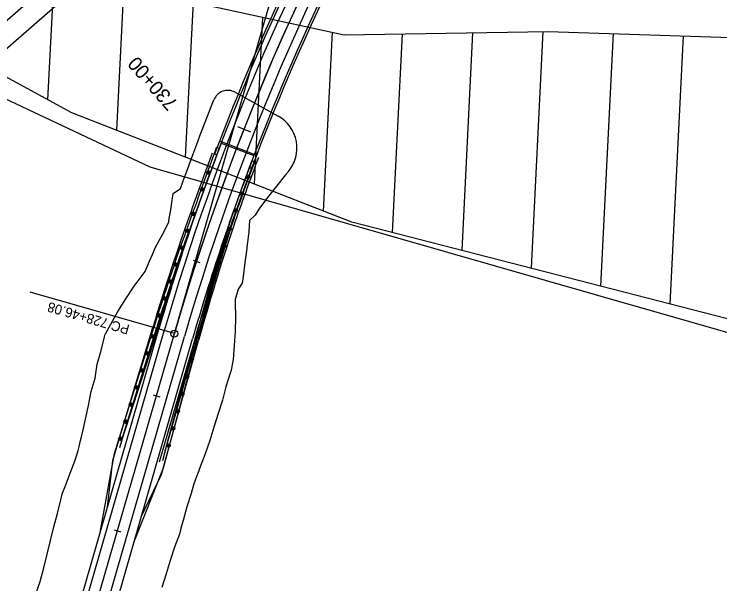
# Model space of a CAD drawing. Extents: x 1300404 to 1323571, y 237813 to 252077.
# Drawn here: x 1311456 to 1311959, y 241084 to 241490 of the extents above; entities that cross this region are included whole.
import ezdxf

# ---------------------------------------------------------------- set-up
doc = ezdxf.new("R2010")
doc.units = 0
for name, color, linetype in [('R_Bridge', 7, 'Continuous'), ('R_Const Limits', 7, 'Continuous'), ('R_Floodway', 7, 'Continuous'), ('R_Flooplain', 7, 'Continuous'), ('R_Future', 7, 'Continuous'), ('R_Guardrail', 7, 'Continuous'), ('R_Horz Alg Annot', 7, 'Continuous'), ('R_Horz Alg Annot Leader', 7, 'Continuous'), ('R_Horz Alg Major Ticks', 7, 'Continuous'), ('R_Horz Alg Minor Ticks', 7, 'Continuous'), ('R_Horz Alg Station Annot', 7, 'Continuous'), ('R_Horz Alg Tangents', 7, 'Continuous'), ('R_Lane Edge', 7, 'Continuous'), ('R_No Plot', 7, 'Continuous'), ('R_Proposed', 7, 'Continuous'), ('R_Shoulder', 7, 'Continuous')]:
    doc.layers.add(name, color=color, linetype=linetype)

msp = doc.modelspace()

# ---------------------------------------------------------------- linework, layer by layer
at = {"layer": 'R_Bridge'}
for p, q in [((1311602.77, 241399.44), (1311629.06, 241389.36)), ((1311603.88, 241397.94), (1311627.23, 241388.99)), ((1311600.69, 241389.53), (1311599.21, 241390.09)), ((1311624.03, 241380.58), (1311625.51, 241380.01))]:
    msp.add_line(p, q, dxfattribs=at)
for radius, start, end in [(1650.1, 149.19442, 159.34505), (1648.52, 149.19413, 159.34535), (1623.52, 149.18931, 159.35016), (1621.94, 149.189, 159.35047)]:
    msp.add_arc((1313143.24, 240808.04), radius, start, end, dxfattribs=at)
at = {"layer": 'R_Const Limits'}
msp.add_line((1311613.83, 241434.11), (1311644.45, 241417.13), dxfattribs=at)
for points in [[(1311471.45, 241076.33), (1311474.97, 241085.72), (1311474.99, 241085.73), (1311477.4, 241095.43), (1311479.82, 241105.14), (1311482.18, 241114.86), (1311484.67, 241124.55), (1311487.13, 241134.25), (1311489.58, 241143.95), (1311490.58, 241147.93), (1311490.62, 241148.06), (1311492.68, 241153.47), (1311496.26, 241162.84), (1311499.85, 241172.21), (1311501.96, 241178.99), (1311502.01, 241179.12), (1311502.67, 241181.81), (1311503.71, 241186.1), (1311504.35, 241188.71), (1311504.38, 241188.84), (1311505.02, 241191.54), (1311507.27, 241201.3), (1311509.24, 241211.14), (1311511.33, 241220.94), (1311513.97, 241230.59), (1311515.53, 241240.55), (1311518.36, 241250.14), (1311520.73, 241259.86), (1311521.3, 241261.88), (1311521.35, 241262), (1311525.14, 241269), (1311530.3, 241278.02), (1311535.88, 241287.07), (1311541.87, 241295.95), (1311548.28, 241304.67), (1311549.68, 241306.48), (1311549.76, 241306.59), (1311552.86, 241313.92), (1311554.87, 241318.63), (1311556.9, 241323.33), (1311561.71, 241332.46), (1311566.48, 241341.6), (1311566.65, 241342.7), (1311568.12, 241351.79), (1311568.47, 241353.93), (1311568.49, 241354.06), (1311569.72, 241362.02), (1311574.88, 241365.59), (1311576.59, 241370.38), (1311580.06, 241379.94), (1311583.58, 241389.47), (1311587.16, 241398.99), (1311588.97, 241403.74), (1311590.8, 241408.48), (1311598.66, 241428.64), (1311598.66, 241428.64)], [(1311651.8, 241377.7), (1311649.74, 241375.23), (1311643.19, 241367.25), (1311636.81, 241359.17), (1311630.68, 241350.96), (1311628.12, 241346.66), (1311624.12, 241342.86), (1311623.65, 241334.94), (1311623.63, 241334.81), (1311623.36, 241332.72), (1311622.25, 241323.84), (1311622.11, 241322.77), (1311620.76, 241312.88), (1311619.48, 241303), (1311618.86, 241298.06), (1311615.95, 241293.85), (1311613.89, 241286.52), (1311613.85, 241286.4), (1311613.91, 241284.23), (1311614, 241273.97), (1311613.78, 241263.85), (1311613.2, 241253.87), (1311612.37, 241243.8), (1311610.96, 241236.12), (1311610.94, 241235.99), (1311610.37, 241233.98), (1311607.26, 241224.46), (1311604.69, 241214.8), (1311601.67, 241205.26), (1311598.67, 241195.72), (1311595.79, 241186.14), (1311592.51, 241176.68), (1311588.96, 241167.3), (1311587.96, 241164.7), (1311587.91, 241164.58), (1311586.96, 241162.05), (1311585.43, 241157.91), (1311584.47, 241155.3), (1311584.43, 241155.18), (1311582.4, 241148.37), (1311579.42, 241138.82), (1311576.7, 241129.2), (1311575.17, 241123.64), (1311575.13, 241123.51), (1311574.18, 241119.52), (1311570.7, 241110.12), (1311567.48, 241100.64), (1311564.58, 241091.07), (1311561.49, 241081.55)]]:
    msp.add_lwpolyline(points, dxfattribs=at)
for centre, radius, start, end in [((1311608.64, 241424.75), 10.71, 60.988, 158.6797), ((1311631.83, 241394.38), 26.02, 320.149, 60.988)]:
    msp.add_arc(centre, radius, start, end, dxfattribs=at)
at = {"layer": 'R_Floodway'}
for p, q in [((1311480.45, 241428.78), (1311486.99, 241559.2)), ((1311529.43, 241407.02), (1311534.97, 241517.61)), ((1311578.53, 241387.86), (1311584.07, 241498.53)), ((1311627.63, 241368.7), (1311633.59, 241487.69)), ((1311676.74, 241349.54), (1311683.11, 241476.85)), ((1311775.45, 241321.47), (1311783.22, 241476.52)), ((1311824.88, 241308.75), (1311833.33, 241477.33)), ((1311726.03, 241334.18), (1311733.12, 241475.7)), ((1311874.31, 241296.04), (1311883.31, 241475.86)), ((1311923.73, 241283.32), (1311933.3, 241474.22))]:
    msp.add_line(p, q, dxfattribs=at)
for points in [[(1313830.5, 242013.29), (1313725.05, 241936.34), (1313624.18, 241854.31), (1313605.13, 241763.33), (1313491.24, 241614.21), (1313390.85, 241541.84), (1313238.35, 241394.67), (1313129.75, 241351.75), (1313002.33, 241319.46), (1312893.25, 241266.88), (1312749.18, 241191.87), (1312719.26, 241174.03), (1312375.34, 241167.16), (1311696.89, 241341.68), (1311497.53, 241419.47), (1311333.82, 241508.77), (1311059.08, 241652.06), (1310740.78, 241795.13), (1310453.25, 241924.55), (1310367.2, 241994.21), (1310267.81, 242111.73), (1309996.24, 242391.57), (1309869.69, 242546.75), (1309624.53, 242919.62)], [(1310379.63, 242680.75), (1310490.18, 242568.72), (1310548.96, 242534.3), (1310676.05, 242414.18), (1310731.56, 242362.99), (1310810.26, 242291.28), (1310887.62, 242241.41), (1310974.87, 242195.88), (1311031.59, 242168.82), (1311109.67, 242133.43), (1311173.76, 242108.43), (1311242.66, 242083.18), (1311339.33, 242032.34), (1311351.04, 242024.49), (1311431.54, 241940.59), (1311405.15, 241750.77), (1311416.02, 241677.63), (1311441.14, 241598.94), (1311547.83, 241506.46), (1311691.44, 241475.03), (1311836.73, 241477.39), (1311974.41, 241472.87)]]:
    msp.add_lwpolyline(points, dxfattribs=at)
at = {"layer": 'R_Flooplain'}
msp.add_lwpolyline([(1309009.78, 242685.04), (1309044.07, 242596.21), (1309055.9, 242542.38), (1309352.07, 242367.77), (1309503.16, 242292.41), (1309669.46, 242230.8), (1309815.49, 242150.85), (1309936.66, 242057.64), (1310419.39, 241839.75), (1310733.16, 241727.16), (1311043.67, 241597.79), (1311103.17, 241577.86), (1311152.77, 241553.58), (1311178, 241525.7), (1311328.48, 241486.66), (1311553.07, 241380.98), (1311870.34, 241289.99), (1312137.52, 241213.62)], dxfattribs=at)
at = {"layer": 'R_Future'}
for p, q in [((1311720.02, 241720.22), (1309955.69, 240177.48)), ((1311729.9, 241708.92), (1311093.16, 241152.15))]:
    msp.add_line(p, q, dxfattribs=at)
at = {"layer": 'R_Guardrail'}
for p, q in [((1311596.03, 241376.79), (1311594.04, 241375.87)), ((1311621.68, 241373.9), (1311623.67, 241374.83)), ((1311591.65, 241364.84), (1311589.66, 241363.92)), ((1311617.32, 241361.94), (1311619.31, 241362.87)), ((1311612.97, 241349.98), (1311614.96, 241350.91)), ((1311585.33, 241347.35), (1311583.35, 241346.42)), ((1311563.52, 241176.82), (1311610.9, 241344.46)), ((1311608.49, 241336.87), (1311610.45, 241337.86)), ((1311581.03, 241335.37), (1311579.05, 241334.44)), ((1311604.74, 241324.71), (1311606.67, 241325.73)), ((1311576.74, 241323.39), (1311574.76, 241322.46)), ((1311574.79, 241315.55), (1311532.83, 241185.87)), ((1311532.83, 241185.87), (1311574.79, 241315.55)), ((1311572.51, 241311.39), (1311570.56, 241310.4)), ((1311600.99, 241312.55), (1311602.93, 241313.57)), ((1311597.25, 241300.38), (1311599.19, 241301.41)), ((1311568.52, 241299.3), (1311566.56, 241298.32)), ((1311564.52, 241287.22), (1311562.56, 241286.24)), ((1311593.73, 241288.15), (1311595.64, 241289.23)), ((1311560.53, 241275.13), (1311558.59, 241274.12)), ((1311590.29, 241275.9), (1311592.2, 241276.97)), ((1311532.83, 241185.87), (1311557.69, 241265.93)), ((1311555.9, 241260.31), (1311553.96, 241259.29)), ((1311586.86, 241263.65), (1311588.77, 241264.72)), ((1311584.98, 241258.05), (1311559.78, 241170.78)), ((1311563.52, 241176.82), (1311585.21, 241257.98)), ((1311584.81, 241256.28), (1311586.71, 241257.37)), ((1311552.12, 241248.15), (1311550.18, 241247.13)), ((1311581.52, 241243.98), (1311583.42, 241245.08)), ((1311548.35, 241236), (1311546.41, 241234.98)), ((1311578.24, 241231.69), (1311580.14, 241232.78)), ((1311544.57, 241223.85), (1311542.63, 241222.83)), ((1311574.95, 241219.39), (1311576.85, 241220.49)), ((1311540.8, 241211.69), (1311538.86, 241210.67)), ((1311571.67, 241207.1), (1311573.56, 241208.19)), ((1311537.02, 241199.54), (1311535.08, 241198.52)), ((1311568.38, 241194.8), (1311570.28, 241195.9)), ((1311533.25, 241187.38), (1311531.31, 241186.36)), ((1311565.09, 241182.51), (1311566.99, 241183.6))]:
    msp.add_line(p, q, dxfattribs=at)
for points in [[(1311602.48, 241394.27), (1311588.39, 241355.8), (1311587.37, 241352.89)], [(1311602.48, 241394.27), (1311588.39, 241355.8), (1311587.37, 241352.89)], [(1311602.48, 241394.27), (1311598.1, 241382.32)], [(1311598.1, 241382.32), (1311593.73, 241370.37)], [(1311610.9, 241344.46), (1311624.82, 241382.66), (1311625.79, 241385.22)], [(1311610.9, 241344.46), (1311624.82, 241382.66), (1311625.79, 241385.22)], [(1311595.67, 241377.72), (1311593.56, 241376.74)], [(1311595.21, 241378.05), (1311593.61, 241377.31)], [(1311595.95, 241377.3), (1311593.7, 241376.26)], [(1311595.77, 241376.09), (1311594.74, 241375.61)], [(1311619.61, 241368.37), (1311623.97, 241380.33)], [(1311621.76, 241373.39), (1311624, 241374.44)], [(1311621.94, 241374.6), (1311622.96, 241375.08)], [(1311622.03, 241372.97), (1311624.15, 241373.96)], [(1311622.5, 241372.64), (1311624.1, 241373.39)], [(1311591.3, 241365.77), (1311589.18, 241364.79)], [(1311590.83, 241366.1), (1311589.23, 241365.36)], [(1311593.73, 241370.37), (1311589.35, 241358.42)], [(1311615.26, 241356.41), (1311619.61, 241368.37)], [(1311591.57, 241365.35), (1311589.32, 241364.31)], [(1311591.39, 241364.14), (1311590.37, 241363.66)], [(1311617.4, 241361.43), (1311619.65, 241362.48)], [(1311617.58, 241362.65), (1311618.61, 241363.12)], [(1311617.68, 241361.01), (1311619.79, 241362)], [(1311618.14, 241360.69), (1311619.75, 241361.43)], [(1311610.9, 241344.46), (1311615.26, 241356.41)], [(1311587.37, 241352.89), (1311573.54, 241314.32), (1311560.67, 241275.41), (1311557.69, 241265.93)], [(1311587.37, 241352.89), (1311573.54, 241314.32), (1311560.67, 241275.41), (1311557.69, 241265.93)], [(1311587.37, 241352.89), (1311583.07, 241340.91)], [(1311613.23, 241350.69), (1311614.25, 241351.17)], [(1311584.97, 241348.28), (1311582.86, 241347.28)], [(1311584.5, 241348.6), (1311582.9, 241347.85)], [(1311585.25, 241347.86), (1311583.01, 241346.8)], [(1311585.08, 241346.64), (1311584.05, 241346.16)], [(1311613.05, 241349.48), (1311615.29, 241350.52)], [(1311613.32, 241349.06), (1311615.44, 241350.04)], [(1311613.79, 241348.73), (1311615.39, 241349.47)], [(1311583.07, 241340.91), (1311578.78, 241328.93)], [(1311585.21, 241257.98), (1311596.19, 241297.11), (1311608.14, 241335.95), (1311610.9, 241344.46)], [(1311585.21, 241257.98), (1311596.19, 241297.11), (1311608.14, 241335.95), (1311610.9, 241344.46)], [(1311606.62, 241331.27), (1311610.55, 241343.38)], [(1311580.67, 241336.3), (1311578.56, 241335.3)], [(1311580.21, 241336.62), (1311578.61, 241335.87)], [(1311580.95, 241335.88), (1311578.71, 241334.82)], [(1311608.59, 241336.36), (1311610.8, 241337.49)], [(1311608.72, 241337.58), (1311609.73, 241338.09)], [(1311608.88, 241335.95), (1311610.96, 241337.01)], [(1311609.36, 241335.64), (1311610.93, 241336.44)], [(1311580.78, 241334.67), (1311579.76, 241334.18)], [(1311602.95, 241319.08), (1311606.7, 241331.25)], [(1311578.78, 241328.93), (1311574.48, 241316.95)], [(1311604.96, 241325.43), (1311605.96, 241325.96)], [(1311576.38, 241324.32), (1311574.27, 241323.32)], [(1311575.91, 241324.64), (1311574.31, 241323.89)], [(1311576.65, 241323.9), (1311574.42, 241322.84)], [(1311576.49, 241322.69), (1311575.46, 241322.2)], [(1311604.84, 241324.21), (1311607.03, 241325.36)], [(1311605.14, 241323.8), (1311607.2, 241324.89)], [(1311605.62, 241323.5), (1311607.18, 241324.32)], [(1311574.42, 241316.97), (1311570.42, 241304.89)], [(1311599.21, 241306.92), (1311602.95, 241319.08)], [(1311572.13, 241312.3), (1311570.05, 241311.25)], [(1311571.66, 241312.62), (1311570.08, 241311.82)], [(1311572.42, 241311.89), (1311570.21, 241310.78)], [(1311572.28, 241310.67), (1311571.27, 241310.17)], [(1311601.1, 241312.04), (1311603.29, 241313.2)], [(1311601.21, 241313.26), (1311602.21, 241313.79)], [(1311601.39, 241311.64), (1311603.45, 241312.73)], [(1311601.87, 241311.33), (1311603.44, 241312.16)], [(1311595.47, 241294.76), (1311599.21, 241306.92)], [(1311567.66, 241300.53), (1311566.08, 241299.74)], [(1311570.42, 241304.89), (1311566.42, 241292.81)], [(1311597.36, 241299.88), (1311599.54, 241301.04)], [(1311597.47, 241301.1), (1311598.47, 241301.63)], [(1311597.65, 241299.47), (1311599.71, 241300.57)], [(1311568.14, 241300.22), (1311566.05, 241299.17)], [(1311568.42, 241299.81), (1311566.21, 241298.7)], [(1311568.28, 241298.59), (1311567.27, 241298.08)], [(1311598.13, 241299.17), (1311599.69, 241300)], [(1311566.42, 241292.81), (1311562.43, 241280.72)], [(1311592.09, 241282.49), (1311595.53, 241294.74)], [(1311564.14, 241288.14), (1311562.06, 241287.09)], [(1311563.67, 241288.45), (1311562.09, 241287.66)], [(1311564.43, 241287.73), (1311562.21, 241286.61)], [(1311564.29, 241286.51), (1311563.28, 241286)], [(1311593.85, 241287.65), (1311596.01, 241288.87)], [(1311593.93, 241288.88), (1311594.92, 241289.43)], [(1311594.15, 241287.26), (1311596.19, 241288.4)], [(1311594.64, 241286.96), (1311596.18, 241287.83)], [(1311562.34, 241280.75), (1311558.53, 241268.61)], [(1311588.65, 241270.23), (1311592.09, 241282.49)], [(1311560.13, 241276.05), (1311558.07, 241274.96)], [(1311559.65, 241276.35), (1311558.09, 241275.53)], [(1311560.43, 241275.64), (1311558.23, 241274.49)], [(1311590.41, 241275.4), (1311592.57, 241276.61)], [(1311590.49, 241276.62), (1311591.48, 241277.18)], [(1311590.72, 241275), (1311592.75, 241276.15)], [(1311591.2, 241274.71), (1311592.75, 241275.58)], [(1311560.31, 241274.42), (1311559.3, 241273.9)], [(1311585.21, 241257.98), (1311588.65, 241270.23)], [(1311557.69, 241265.93), (1311532.83, 241185.87)], [(1311557.69, 241265.93), (1311532.83, 241185.87)], [(1311557.69, 241265.93), (1311553.92, 241253.77)], [(1311555.5, 241261.22), (1311553.43, 241260.13)], [(1311555.02, 241261.52), (1311553.45, 241260.7)], [(1311555.79, 241260.81), (1311553.6, 241259.66)], [(1311583.24, 241250.59), (1311586.52, 241262.88)], [(1311586.97, 241263.15), (1311589.13, 241264.36)], [(1311587.06, 241264.37), (1311588.04, 241264.92)], [(1311587.28, 241262.75), (1311589.31, 241263.89)], [(1311587.77, 241262.46), (1311589.31, 241263.32)], [(1311555.67, 241259.59), (1311554.67, 241259.06)], [(1311563.52, 241176.82), (1311585.21, 241257.98)], [(1311563.52, 241176.82), (1311585.21, 241257.98)], [(1311584.93, 241255.78), (1311587.08, 241257.01)], [(1311585, 241257), (1311585.98, 241257.57)], [(1311585.24, 241255.38), (1311587.26, 241256.55)], [(1311585.74, 241255.1), (1311587.27, 241255.98)], [(1311553.92, 241253.77), (1311550.14, 241241.62)], [(1311579.95, 241238.29), (1311583.24, 241250.59)], [(1311551.72, 241249.06), (1311549.66, 241247.98)], [(1311551.24, 241249.37), (1311549.68, 241248.55)], [(1311552.02, 241248.66), (1311549.83, 241247.51)], [(1311551.9, 241247.44), (1311550.9, 241246.91)], [(1311581.72, 241244.7), (1311582.7, 241245.27)], [(1311550.14, 241241.62), (1311546.37, 241229.47)], [(1311581.65, 241243.48), (1311583.79, 241244.72)], [(1311581.96, 241243.09), (1311583.98, 241244.26)], [(1311582.45, 241242.8), (1311583.98, 241243.69)], [(1311547.95, 241236.91), (1311545.88, 241235.82)], [(1311547.47, 241237.21), (1311545.9, 241236.39)], [(1311548.24, 241236.5), (1311546.05, 241235.35)], [(1311548.12, 241235.28), (1311547.12, 241234.76)], [(1311576.67, 241226), (1311579.95, 241238.29)], [(1311578.36, 241231.19), (1311580.51, 241232.42)], [(1311578.43, 241232.41), (1311579.41, 241232.98)], [(1311578.67, 241230.79), (1311580.69, 241231.96)], [(1311579.16, 241230.51), (1311580.7, 241231.39)], [(1311543.69, 241225.06), (1311542.13, 241224.24)], [(1311546.37, 241229.47), (1311542.59, 241217.31)], [(1311573.38, 241213.7), (1311576.67, 241226)], [(1311544.17, 241224.75), (1311542.11, 241223.67)], [(1311544.47, 241224.35), (1311542.28, 241223.2)], [(1311544.35, 241223.13), (1311543.35, 241222.6)], [(1311575.08, 241218.89), (1311577.22, 241220.13)], [(1311575.15, 241220.11), (1311576.12, 241220.68)], [(1311542.59, 241217.31), (1311538.82, 241205.16)], [(1311575.39, 241218.5), (1311577.41, 241219.67)], [(1311575.88, 241218.21), (1311577.41, 241219.1)], [(1311540.4, 241212.6), (1311538.33, 241211.51)], [(1311539.92, 241212.91), (1311538.35, 241212.08)], [(1311540.69, 241212.2), (1311538.5, 241211.04)], [(1311540.58, 241210.98), (1311539.57, 241210.45)], [(1311570.09, 241201.41), (1311573.38, 241213.7)], [(1311538.82, 241205.16), (1311535.05, 241193)], [(1311571.79, 241206.6), (1311573.93, 241207.83)], [(1311571.86, 241207.82), (1311572.84, 241208.39)], [(1311572.1, 241206.2), (1311574.12, 241207.37)], [(1311572.59, 241205.92), (1311574.12, 241206.8)], [(1311536.62, 241200.45), (1311534.56, 241199.36)], [(1311536.14, 241200.75), (1311534.58, 241199.93)], [(1311536.92, 241200.04), (1311534.73, 241198.89)], [(1311566.81, 241189.11), (1311570.09, 241201.41)], [(1311536.8, 241198.82), (1311535.8, 241198.3)], [(1311568.51, 241194.3), (1311570.65, 241195.54)], [(1311568.57, 241195.52), (1311569.55, 241196.09)], [(1311568.81, 241193.91), (1311570.83, 241195.08)], [(1311535.05, 241193), (1311531.32, 241181.02)], [(1311569.31, 241193.62), (1311570.84, 241194.51)], [(1311532.85, 241188.29), (1311530.78, 241187.21)], [(1311532.37, 241188.6), (1311530.8, 241187.78)], [(1311533.14, 241187.89), (1311530.95, 241186.74)], [(1311533.03, 241186.67), (1311532.02, 241186.14)], [(1311562.22, 241171.96), (1311566.81, 241189.11)], [(1311565.22, 241182.01), (1311567.36, 241183.24)], [(1311565.29, 241183.23), (1311566.27, 241183.8)], [(1311565.53, 241181.61), (1311567.55, 241182.78)], [(1311566.02, 241181.33), (1311567.55, 241182.21)]]:
    msp.add_lwpolyline(points, dxfattribs=at)
for centre in [(1311594.78, 241376.88), (1311622.93, 241373.82), (1311590.4, 241364.93), (1311618.57, 241361.86), (1311614.22, 241349.9), (1311584.08, 241347.43), (1311579.79, 241335.45), (1311609.74, 241336.83), (1311605.98, 241324.69), (1311575.49, 241323.47), (1311571.27, 241311.43), (1311602.24, 241312.53), (1311567.27, 241299.35), (1311598.5, 241300.36), (1311563.27, 241287.26), (1311594.98, 241288.17), (1311559.28, 241275.16), (1311591.54, 241275.91), (1311554.65, 241260.33), (1311588.1, 241263.66), (1311586.06, 241256.3), (1311550.87, 241248.17), (1311582.77, 241244.01), (1311547.1, 241236.02), (1311579.49, 241231.71), (1311543.32, 241223.87), (1311576.2, 241219.42), (1311539.55, 241211.71), (1311572.92, 241207.12), (1311535.77, 241199.56), (1311569.63, 241194.83), (1311532, 241187.41), (1311566.34, 241182.53)]:
    msp.add_circle(centre, 1.25, dxfattribs=at)
for centre, radius, start, end in [((1313143.24, 240808.04), 1648.52, 159.16916, 162.06984), ((1313143.24, 240808.04), 1648.52, 159.16916, 162.06984), ((1313143.24, 240808.04), 1648.52, 159.16916, 160.7003), ((1313143.25, 240808.04), 1621.94, 159.17523, 163.89183), ((1313143.24, 240808.04), 1623.52, 159.17523, 160.7066), ((1313143.24, 240808.04), 1623.52, 159.17523, 160.7066), ((1313132.75, 240777.02), 1649.19, 159.56286, 162.75549), ((1313152.48, 240839.44), 1622.19, 161.86154, 165.04825)]:
    msp.add_arc(centre, radius, start, end, dxfattribs=at)
at = {"layer": 'R_Horz Alg Annot Leader'}
msp.add_lwpolyline([(1311570.49, 241262.23), (1311467.83, 241291.88)], dxfattribs=at)
at = {"layer": 'R_Horz Alg Major Ticks'}
msp.add_lwpolyline([(1311615.43, 241409.71), (1311624.73, 241406.05)], dxfattribs=at)
at = {"layer": 'R_Horz Alg Minor Ticks'}
for points in [[(1311583.93, 241314.55), (1311588.68, 241313)], [(1311555.31, 241218.65), (1311560.11, 241217.26)], [(1311527.56, 241122.58), (1311532.37, 241121.19)]]:
    msp.add_lwpolyline(points, dxfattribs=at)
at = {"layer": 'R_Horz Alg Tangents'}
msp.add_line((1311570.49, 241262.23), (1311703.85, 241724), dxfattribs=at)
at = {"layer": 'R_Lane Edge'}
for p, q in [((1311460.8, 240909.43), (1311563.29, 241264.31)), ((1311460.8, 240909.43), (1311563.29, 241264.31)), ((1311475.21, 240905.27), (1311577.7, 241260.15))]:
    msp.add_line(p, q, dxfattribs=at)
for radius, start in [(1629.52, 131.16667), (1644.52, 136.45181), (1644.52, 136.45181)]:
    msp.add_arc((1313143.24, 240808.04), radius, start, 163.89183, dxfattribs=at)
at = {"layer": 'R_No Plot'}
for p, q in [((1311600.61, 241394.98), (1311602.48, 241394.27)), ((1311627.65, 241384.5), (1311625.79, 241385.22)), ((1311527.94, 241176.87), (1311555.78, 241266.52)), ((1311562.86, 241166.6), (1311587.15, 241257.46)), ((1311517.6, 241120.52), (1311527.94, 241176.87)), ((1311541.57, 241113.42), (1311562.86, 241166.6))]:
    msp.add_line(p, q, dxfattribs=at)
for centre, radius, start, end in [((1313143.24, 240808.04), 1650.52, 159.16916, 160.69961), ((1313143.24, 240808.04), 1621.52, 159.17523, 160.70588), ((1313132.75, 240777.02), 1651.19, 159.56355, 162.75549), ((1313152.48, 240839.44), 1620.19, 161.86226, 165.04825)]:
    msp.add_arc(centre, radius, start, end, dxfattribs=at)
at = {"layer": 'R_Proposed'}
msp.add_line((1311468.01, 240907.35), (1311570.49, 241262.23), dxfattribs=at)
msp.add_circle((1311570.49, 241262.23), 2.5, dxfattribs=at)
for end in [163.89183, 163.04191]:
    msp.add_arc((1313143.24, 240808.04), 1637.02, 131.16667, end, dxfattribs=at)
at = {"layer": 'R_Shoulder'}
for p, q in [((1311456.96, 240910.54), (1311559.45, 241265.42)), ((1311529.51, 241181.58), (1311555.13, 241266.66)), ((1311480.98, 240903.6), (1311583.46, 241258.48)), ((1311564.06, 241171.47), (1311587.77, 241257.24)), ((1311526.73, 241171.97), (1311529.51, 241181.58)), ((1311522.86, 241138.74), (1311526.73, 241171.97)), ((1311561.29, 241161.86), (1311564.06, 241171.47)), ((1311546.85, 241131.68), (1311561.29, 241161.86))]:
    msp.add_line(p, q, dxfattribs=at)
for centre, radius, start, end in [((1313143.24, 240808.04), 1648.52, 159.03254, 163.89183), ((1313143.24, 240808.04), 1652.02, 159.34544, 160.8767), ((1313143.24, 240808.04), 1623.52, 159.03254, 163.89183), ((1313143.24, 240808.04), 1620.02, 159.03254, 160.88125), ((1313138.89, 240789.72), 1654.02, 160.22537, 163.24051), ((1313147.31, 240826.19), 1618.02, 161.53906, 164.54964)]:
    msp.add_arc(centre, radius, start, end, dxfattribs=at)

# ---------------------------------------------------------------- texts
at = {"layer": 'R_Horz Alg Annot'}
msp.add_text('PC 728+46.08', height=7, rotation=163.8918, dxfattribs=at).set_placement((1311539.09, 241268.21))
at = {"layer": 'R_Horz Alg Station Annot'}
msp.add_text('730+00', height=10, rotation=131.1667, dxfattribs=at).set_placement((1311573.58, 241426.59))

doc.saveas('drawing.dxf')
